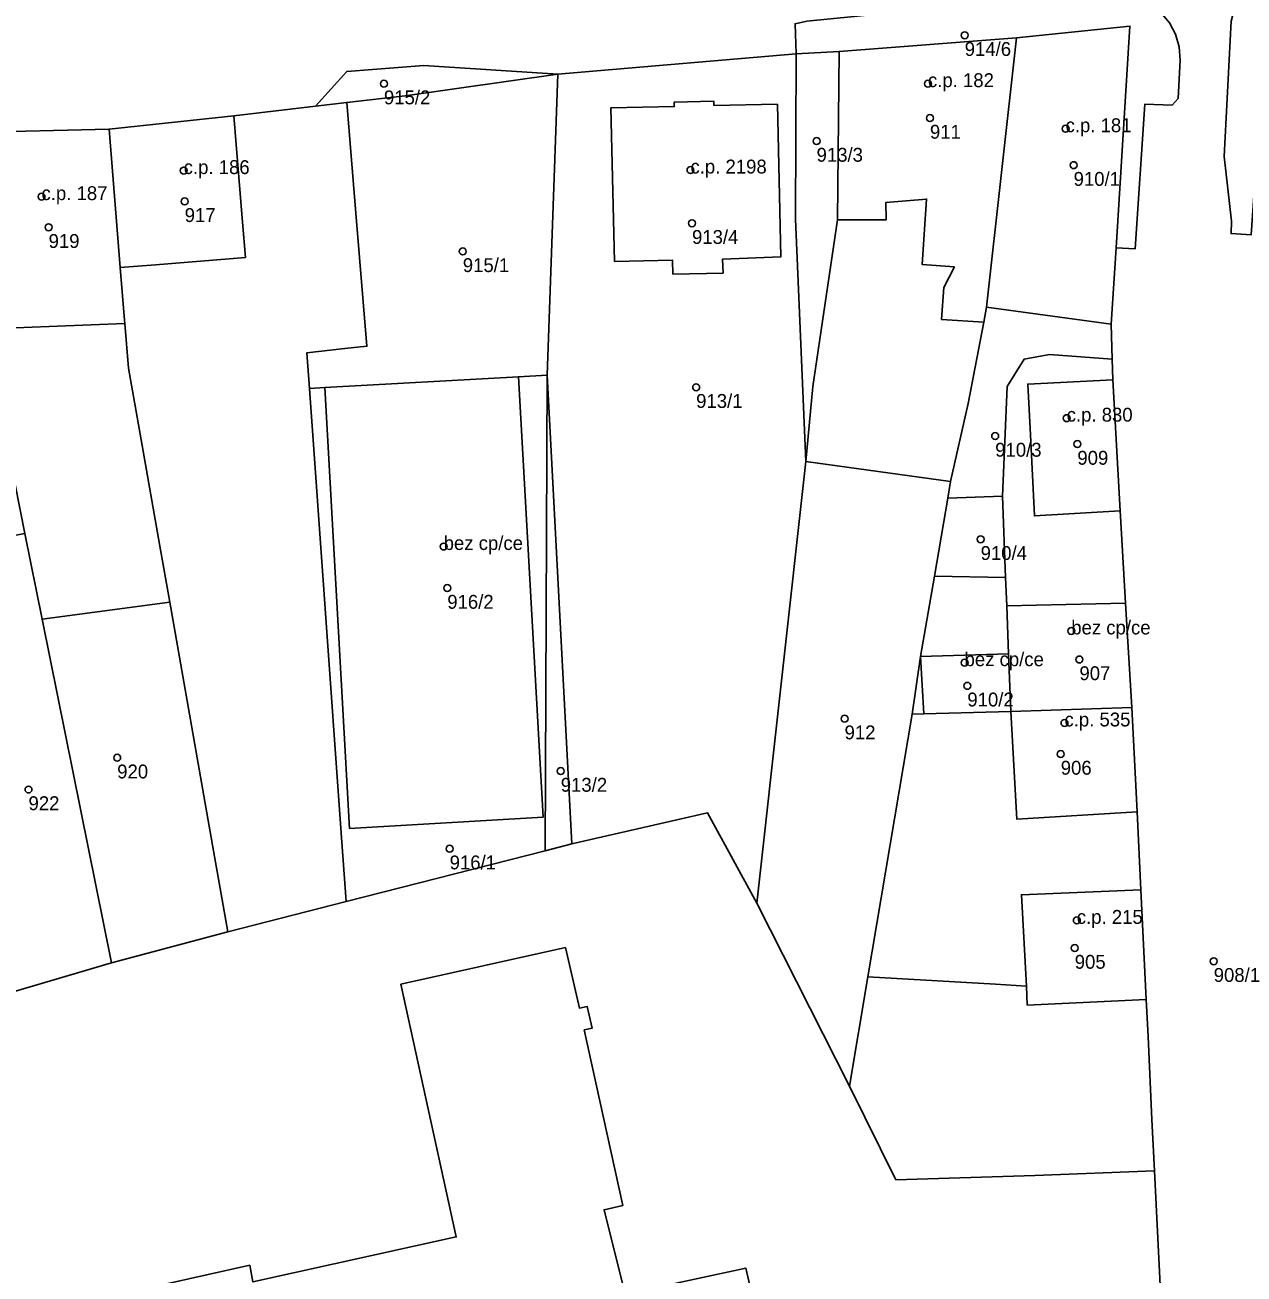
# Model space of a CAD drawing. Extents: x -878211 to -870363, y -1058464 to -1052522.
# Drawn here: x -874758.5 to -874670.5, y -1056399.5 to -1056309.4 of the extents above; entities that cross this region are included whole.
import ezdxf

# ---------------------------------------------------------------- set-up
doc = ezdxf.new("R2010")
doc.units = 0
for name, color, linetype in [('Definiční body', 7, 'Continuous'), ('Polygon budovy', 7, 'Continuous'), ('Polygon parcely', 7, 'Continuous')]:
    doc.layers.add(name, color=color, linetype=linetype)

msp = doc.modelspace()

# ---------------------------------------------------------------- linework, layer by layer
at = {"layer": 'Definiční body'}
for centre in [(-874690.7, -1056310.14994), (-874732.61, -1056313.63994), (-874693.35, -1056313.63994), (-874693.21, -1056316.11994), (-874683.42, -1056316.88994), (-874701.39, -1056317.77994), (-874710.49, -1056319.86994), (-874682.84, -1056319.51994), (-874747.06, -1056319.90994), (-874757.32, -1056321.78994), (-874746.99, -1056322.12994), (-874756.81, -1056323.99994), (-874710.38, -1056323.70994), (-874726.92, -1056325.73994), (-874710.08, -1056335.53994), (-874683.34, -1056337.76994), (-874688.5, -1056339.05994), (-874682.57, -1056339.63994), (-874689.55, -1056346.50994), (-874728.3, -1056347.02994), (-874728.04, -1056350.02994), (-874683.01, -1056353.11994), (-874690.71, -1056355.40994), (-874682.42, -1056355.17994), (-874690.51, -1056357.07994), (-874699.37, -1056359.44994), (-874683.5, -1056359.75994), (-874683.77, -1056361.99994), (-874751.86, -1056362.26994), (-874719.85, -1056363.22994), (-874758.26, -1056364.55994), (-874727.87, -1056368.82994), (-874682.61, -1056373.99994), (-874682.76, -1056375.99994), (-874672.73, -1056376.94994)]:
    msp.add_circle(centre, 0.25, dxfattribs=at)
at = {"layer": 'Polygon budovy'}
for points in [[(-874689.13, -1056329.76), (-874680.13, -1056331), (-874679.78, -1056325.47), (-874678.78, -1056309.49), (-874686.97, -1056310.34)], [(-874691.44, -1056326.86), (-874692.21, -1056328.35), (-874692.37, -1056330.64), (-874689.33, -1056330.85), (-874689.13, -1056329.76), (-874686.97, -1056310.34), (-874699.75, -1056311.33), (-874699.87, -1056323.46), (-874696.36, -1056323.46), (-874696.39, -1056322.2), (-874693.45, -1056321.97), (-874693.77, -1056326.68)], [(-874715.97, -1056326.47), (-874711.78, -1056326.38), (-874711.76, -1056327.38), (-874708.14, -1056327.3), (-874708.18, -1056326.3), (-874703.97, -1056326.14), (-874704.22, -1056315.12), (-874708.8, -1056315.21), (-874708.81, -1056314.9), (-874711.67, -1056314.98), (-874711.66, -1056315.29), (-874716.24, -1056315.39)], [(-874743.44, -1056315.96), (-874752.45, -1056316.91), (-874751.64, -1056326.89), (-874749.09, -1056326.72), (-874742.61, -1056326.17), (-874742.82, -1056323.62)], [(-874762.49, -1056317.15), (-874761.05, -1056331.33), (-874751.31, -1056330.95), (-874751.33, -1056330.7), (-874751.64, -1056326.89), (-874752.45, -1056316.91)], [(-874736.87, -1056335.55), (-874735.09, -1056367.36), (-874721.12, -1056366.55), (-874722.9, -1056334.78)], [(-874680.02, -1056335), (-874686.15, -1056335.31), (-874685.96, -1056338.97), (-874685.67, -1056344.82), (-874679.48, -1056344.46)], [(-874687.67, -1056351.3), (-874687.54, -1056354.78), (-874687.38, -1056358.92), (-874678.65, -1056358.64), (-874679.09, -1056351.11)], [(-874687.54, -1056354.78), (-874693.9, -1056354.96), (-874693.66, -1056359.1), (-874687.38, -1056358.92)], [(-874687.38, -1056358.92), (-874686.93, -1056366.7), (-874678.26, -1056366.18), (-874678.65, -1056358.64)], [(-874677.6, -1056379.71), (-874677.98, -1056371.8), (-874686.61, -1056372.15), (-874686.25, -1056378.74), (-874686.19, -1056380.11)], [(-874755.71, -1056401.89), (-874753.87, -1056410.16), (-874740.43, -1056407.2), (-874740.68, -1056406.06), (-874737.02, -1056405.23), (-874735.99, -1056410.13), (-874722.54, -1056407.16), (-874722.77, -1056406.07), (-874719.12, -1056405.28), (-874718, -1056410.18), (-874704.6, -1056407.31), (-874706.5, -1056399.08), (-874715.2, -1056400.96), (-874716.72, -1056394.87), (-874715.37, -1056394.56), (-874718.16, -1056381.9), (-874717.58, -1056381.77), (-874717.94, -1056380.22), (-874718.5, -1056380.33), (-874719.51, -1056375.96), (-874731.39, -1056378.61), (-874727.39, -1056396.83), (-874742.06, -1056400.08), (-874742.3, -1056398.88)]]:
    msp.add_lwpolyline(points, close=True, dxfattribs=at)
at = {"layer": 'Polygon parcely'}
for points in [[(-874671.98, -1056318.9), (-874671.44, -1056323.57), (-874671.48, -1056324.45), (-874670.03, -1056324.55), (-874669.89, -1056322.45), (-874669.04, -1056309.97), (-874667.58, -1056308.54), (-874661.06, -1056308.27), (-874652.7, -1056307.88), (-874639.53, -1056307.88), (-874634.61, -1056308.52), (-874634.55, -1056306.42), (-874639.68, -1056306.57), (-874647.74, -1056306.28), (-874658.74, -1056306.11), (-874668.48, -1056306.3), (-874669.52, -1056306.48), (-874670.54, -1056307.09), (-874671.17, -1056307.93), (-874671.48, -1056309.14)], [(-874677.71, -1056315.12), (-874675.74, -1056315.2), (-874675.29, -1056314.7), (-874675.14, -1056311.95), (-874675.22, -1056310.99), (-874675.49, -1056310.07), (-874675.91, -1056309.25), (-874676.75, -1056308.3), (-874677.84, -1056307.55), (-874678.94, -1056307.12), (-874680.13, -1056306.95), (-874702.09, -1056309.12), (-874702.94, -1056309.32), (-874702.87, -1056311.49), (-874699.75, -1056311.33), (-874686.97, -1056310.34), (-874678.78, -1056309.49), (-874679.78, -1056325.47), (-874678.39, -1056325.55)], [(-874679.78, -1056325.47), (-874678.78, -1056309.49), (-874686.97, -1056310.34), (-874689.13, -1056329.76), (-874680.13, -1056331)], [(-874686.97, -1056310.34), (-874699.75, -1056311.33), (-874699.87, -1056323.46), (-874701.66, -1056335.49), (-874702.17, -1056340.9), (-874691.72, -1056342.35), (-874690.45, -1056336.7), (-874689.33, -1056330.85), (-874689.13, -1056329.76)], [(-874720.05, -1056312.96), (-874720.83, -1056334.67), (-874719.04, -1056368.48), (-874709.26, -1056366.25), (-874705.69, -1056372.77), (-874702.17, -1056340.9), (-874702.91, -1056323.42), (-874702.87, -1056311.49)], [(-874702.87, -1056311.49), (-874702.91, -1056323.42), (-874702.17, -1056340.9), (-874701.66, -1056335.49), (-874699.87, -1056323.46), (-874699.75, -1056311.33)], [(-874731.09, -1056314.51), (-874720.05, -1056312.96), (-874729.74, -1056312.34), (-874735.29, -1056312.76), (-874737.56, -1056315.27), (-874735.3, -1056315)], [(-874722.9, -1056334.78), (-874720.83, -1056334.67), (-874720.05, -1056312.96), (-874731.09, -1056314.51), (-874735.3, -1056315), (-874734.63, -1056322.98), (-874733.84, -1056332.58), (-874735.43, -1056332.75), (-874738.17, -1056333.05), (-874737.99, -1056335.62), (-874736.87, -1056335.55)], [(-874752.45, -1056316.91), (-874751.64, -1056326.89), (-874751.33, -1056330.7), (-874751.31, -1056330.95), (-874751.05, -1056334.17), (-874750.14, -1056339.33), (-874748.8, -1056346.87), (-874748.07, -1056351.04), (-874744.9, -1056368.99), (-874743.87, -1056374.83), (-874735.34, -1056372.63), (-874735.72, -1056367.37), (-874737.99, -1056335.62), (-874738.17, -1056333.05), (-874735.43, -1056332.75), (-874733.84, -1056332.58), (-874734.63, -1056322.98), (-874735.3, -1056315), (-874737.56, -1056315.27), (-874743.44, -1056315.96)], [(-874715.97, -1056326.47), (-874716.24, -1056315.39), (-874711.66, -1056315.29), (-874711.67, -1056314.98), (-874708.81, -1056314.9), (-874708.8, -1056315.21), (-874704.22, -1056315.12), (-874703.97, -1056326.14), (-874708.18, -1056326.3), (-874708.14, -1056327.3), (-874711.76, -1056327.38), (-874711.78, -1056326.38)], [(-874715.97, -1056326.47), (-874711.78, -1056326.38), (-874711.76, -1056327.38), (-874708.14, -1056327.3), (-874708.18, -1056326.3), (-874703.97, -1056326.14), (-874704.22, -1056315.12), (-874708.8, -1056315.21), (-874708.81, -1056314.9), (-874711.67, -1056314.98), (-874711.66, -1056315.29), (-874716.24, -1056315.39)], [(-874757.27, -1056352.27), (-874748.07, -1056351.04), (-874748.8, -1056346.87), (-874750.14, -1056339.33), (-874751.05, -1056334.17), (-874751.31, -1056330.95), (-874751.33, -1056330.7), (-874751.64, -1056326.89), (-874752.45, -1056316.91), (-874762.49, -1056317.15), (-874761.05, -1056331.33), (-874760.6, -1056335.72), (-874760.27, -1056337.19), (-874758.52, -1056346.1)], [(-874680.07, -1056333.51), (-874680.13, -1056331), (-874689.13, -1056329.76), (-874689.33, -1056330.85), (-874690.45, -1056336.7), (-874691.72, -1056342.35), (-874691.92, -1056343.53), (-874687.97, -1056343.39), (-874687.64, -1056335.48), (-874686.42, -1056333.52), (-874684.57, -1056333.18)], [(-874679.48, -1056344.46), (-874680.02, -1056335), (-874680.07, -1056333.51), (-874684.57, -1056333.18), (-874686.42, -1056333.52), (-874687.64, -1056335.48), (-874687.97, -1056343.39), (-874687.75, -1056349.27), (-874687.67, -1056351.3), (-874679.09, -1056351.11)], [(-874720.98, -1056368.98), (-874720.83, -1056334.67), (-874722.9, -1056334.78), (-874721.12, -1056366.55), (-874735.09, -1056367.36), (-874736.87, -1056335.55), (-874737.99, -1056335.62), (-874735.72, -1056367.37), (-874735.34, -1056372.63)], [(-874736.87, -1056335.55), (-874735.09, -1056367.36), (-874721.12, -1056366.55), (-874722.9, -1056334.78)], [(-874719.04, -1056368.48), (-874720.83, -1056334.67), (-874720.98, -1056368.98)], [(-874705.69, -1056372.77), (-874699.02, -1056385.96), (-874697.68, -1056378.07), (-874694.48, -1056359.13), (-874693.9, -1056354.96), (-874692.89, -1056349.16), (-874691.92, -1056343.53), (-874691.72, -1056342.35), (-874702.17, -1056340.9)], [(-874691.92, -1056343.53), (-874692.89, -1056349.16), (-874687.75, -1056349.27), (-874687.97, -1056343.39)], [(-874759.61, -1056379.22), (-874752.26, -1056377.07), (-874757.27, -1056352.27), (-874758.52, -1056346.1), (-874761.36, -1056346.61), (-874764.24, -1056346.44), (-874767.09, -1056346.97)], [(-874693.9, -1056354.96), (-874694.48, -1056359.13), (-874693.66, -1056359.1), (-874687.38, -1056358.92), (-874687.54, -1056354.78), (-874687.67, -1056351.3), (-874687.75, -1056349.27), (-874692.89, -1056349.16)], [(-874752.26, -1056377.07), (-874743.87, -1056374.83), (-874744.9, -1056368.99), (-874748.07, -1056351.04), (-874757.27, -1056352.27)], [(-874679.09, -1056351.11), (-874687.67, -1056351.3), (-874687.54, -1056354.78), (-874687.38, -1056358.92), (-874678.65, -1056358.64)], [(-874678.65, -1056358.64), (-874687.38, -1056358.92), (-874693.66, -1056359.1), (-874694.48, -1056359.13), (-874697.68, -1056378.07), (-874688.47, -1056378.61), (-874686.25, -1056378.74), (-874686.61, -1056372.15), (-874677.98, -1056371.8), (-874678.26, -1056366.18)], [(-874676.37, -1056404.7), (-874677.01, -1056392.06), (-874685.65, -1056392.4), (-874695.66, -1056392.71), (-874699.02, -1056385.96), (-874705.69, -1056372.77), (-874709.26, -1056366.25), (-874719.04, -1056368.48), (-874720.98, -1056368.98), (-874735.34, -1056372.63), (-874743.87, -1056374.83), (-874752.26, -1056377.07), (-874759.61, -1056379.22), (-874769.04, -1056401.77), (-874773.98, -1056413.47), (-874779.49, -1056427.06), (-874780.55, -1056429.67), (-874762.07, -1056437.23), (-874747.48, -1056443.08), (-874718.21, -1056454.5), (-874706.91, -1056430.53), (-874696.83, -1056406.55), (-874687.37, -1056405.45), (-874685.09, -1056405.18)], [(-874677.6, -1056379.71), (-874677.98, -1056371.8), (-874686.61, -1056372.15), (-874686.25, -1056378.74), (-874688.47, -1056378.61), (-874697.68, -1056378.07), (-874699.02, -1056385.96), (-874695.66, -1056392.71), (-874685.65, -1056392.4), (-874677.01, -1056392.06), (-874677.19, -1056388.36), (-874677.47, -1056382.38)], [(-874719.51, -1056375.96), (-874718.5, -1056380.33), (-874717.94, -1056380.22), (-874717.58, -1056381.77), (-874718.16, -1056381.9), (-874715.37, -1056394.56), (-874716.72, -1056394.87), (-874715.2, -1056400.96), (-874706.5, -1056399.08), (-874704.6, -1056407.31), (-874718, -1056410.18), (-874719.12, -1056405.28), (-874722.77, -1056406.07), (-874722.54, -1056407.16), (-874735.99, -1056410.13), (-874737.02, -1056405.23), (-874740.68, -1056406.06), (-874740.43, -1056407.2), (-874753.87, -1056410.16), (-874755.71, -1056401.89), (-874742.3, -1056398.88), (-874742.06, -1056400.08), (-874727.39, -1056396.83), (-874731.39, -1056378.61)], [(-874719.51, -1056375.96), (-874731.39, -1056378.61), (-874727.39, -1056396.83), (-874742.06, -1056400.08), (-874742.3, -1056398.88), (-874755.71, -1056401.89), (-874753.87, -1056410.16), (-874740.43, -1056407.2), (-874740.68, -1056406.06), (-874737.02, -1056405.23), (-874735.99, -1056410.13), (-874722.54, -1056407.16), (-874722.77, -1056406.07), (-874719.12, -1056405.28), (-874718, -1056410.18), (-874704.6, -1056407.31), (-874706.5, -1056399.08), (-874715.2, -1056400.96), (-874716.72, -1056394.87), (-874715.37, -1056394.56), (-874718.16, -1056381.9), (-874717.58, -1056381.77), (-874717.94, -1056380.22), (-874718.5, -1056380.33)]]:
    msp.add_lwpolyline(points, close=True, dxfattribs=at)
for points in [[(-874670.03, -1056324.55), (-874671.48, -1056324.45), (-874671.44, -1056323.57), (-874671.98, -1056318.9), (-874671.48, -1056309.14), (-874671.17, -1056307.93), (-874670.54, -1056307.09)], [(-874762.49, -1056317.15), (-874752.45, -1056316.91), (-874743.44, -1056315.96), (-874737.56, -1056315.27), (-874735.29, -1056312.76), (-874729.74, -1056312.34), (-874720.05, -1056312.96), (-874702.87, -1056311.49), (-874702.94, -1056309.32)], [(-874675.91, -1056309.25), (-874675.49, -1056310.07), (-874675.22, -1056310.99), (-874675.14, -1056311.95), (-874675.29, -1056314.7), (-874675.74, -1056315.2), (-874677.71, -1056315.12), (-874678.39, -1056325.55), (-874679.78, -1056325.47), (-874680.13, -1056331), (-874680.07, -1056333.51), (-874680.02, -1056335), (-874679.48, -1056344.46), (-874679.09, -1056351.11), (-874678.65, -1056358.64), (-874678.26, -1056366.18), (-874677.98, -1056371.8), (-874677.6, -1056379.71), (-874677.47, -1056382.38), (-874677.19, -1056388.36), (-874677.01, -1056392.06), (-874676.37, -1056404.7)]]:
    msp.add_lwpolyline(points, dxfattribs=at)

# ---------------------------------------------------------------- texts
at = {"layer": 'Definiční body'}
for s, p in [('914/6', (-874690.7, -1056311.639)), ('c.p. 182', (-874693.35, -1056313.889)), ('915/2', (-874732.61, -1056315.129)), ('911', (-874693.21, -1056317.609)), ('c.p. 181', (-874683.42, -1056317.139)), ('913/3', (-874701.39, -1056319.269)), ('c.p. 186', (-874747.06, -1056320.159)), ('c.p. 2198', (-874710.49, -1056320.12)), ('910/1', (-874682.84, -1056321.009)), ('c.p. 187', (-874757.32, -1056322.04)), ('917', (-874746.99, -1056323.619)), ('919', (-874756.81, -1056325.489)), ('913/4', (-874710.38, -1056325.199)), ('915/1', (-874726.92, -1056327.229)), ('913/1', (-874710.08, -1056337.029)), ('c.p. 830', (-874683.34, -1056338.02)), ('910/3', (-874688.5, -1056340.549)), ('909', (-874682.57, -1056341.129)), ('bez cp/ce', (-874728.3, -1056347.28)), ('910/4', (-874689.55, -1056347.999)), ('916/2', (-874728.04, -1056351.519)), ('bez cp/ce', (-874683.01, -1056353.37)), ('bez cp/ce', (-874690.71, -1056355.659)), ('907', (-874682.42, -1056356.669)), ('910/2', (-874690.51, -1056358.569)), ('c.p. 535', (-874683.5, -1056360.01)), ('912', (-874699.37, -1056360.939)), ('920', (-874751.86, -1056363.759)), ('906', (-874683.77, -1056363.489)), ('913/2', (-874719.85, -1056364.719)), ('922', (-874758.26, -1056366.049)), ('916/1', (-874727.87, -1056370.319)), ('c.p. 215', (-874682.61, -1056374.25)), ('905', (-874682.76, -1056377.489)), ('908/1', (-874672.73, -1056378.439))]:
    msp.add_text(s, height=0.999996, dxfattribs=at).set_placement(p)

doc.saveas('drawing.dxf')
